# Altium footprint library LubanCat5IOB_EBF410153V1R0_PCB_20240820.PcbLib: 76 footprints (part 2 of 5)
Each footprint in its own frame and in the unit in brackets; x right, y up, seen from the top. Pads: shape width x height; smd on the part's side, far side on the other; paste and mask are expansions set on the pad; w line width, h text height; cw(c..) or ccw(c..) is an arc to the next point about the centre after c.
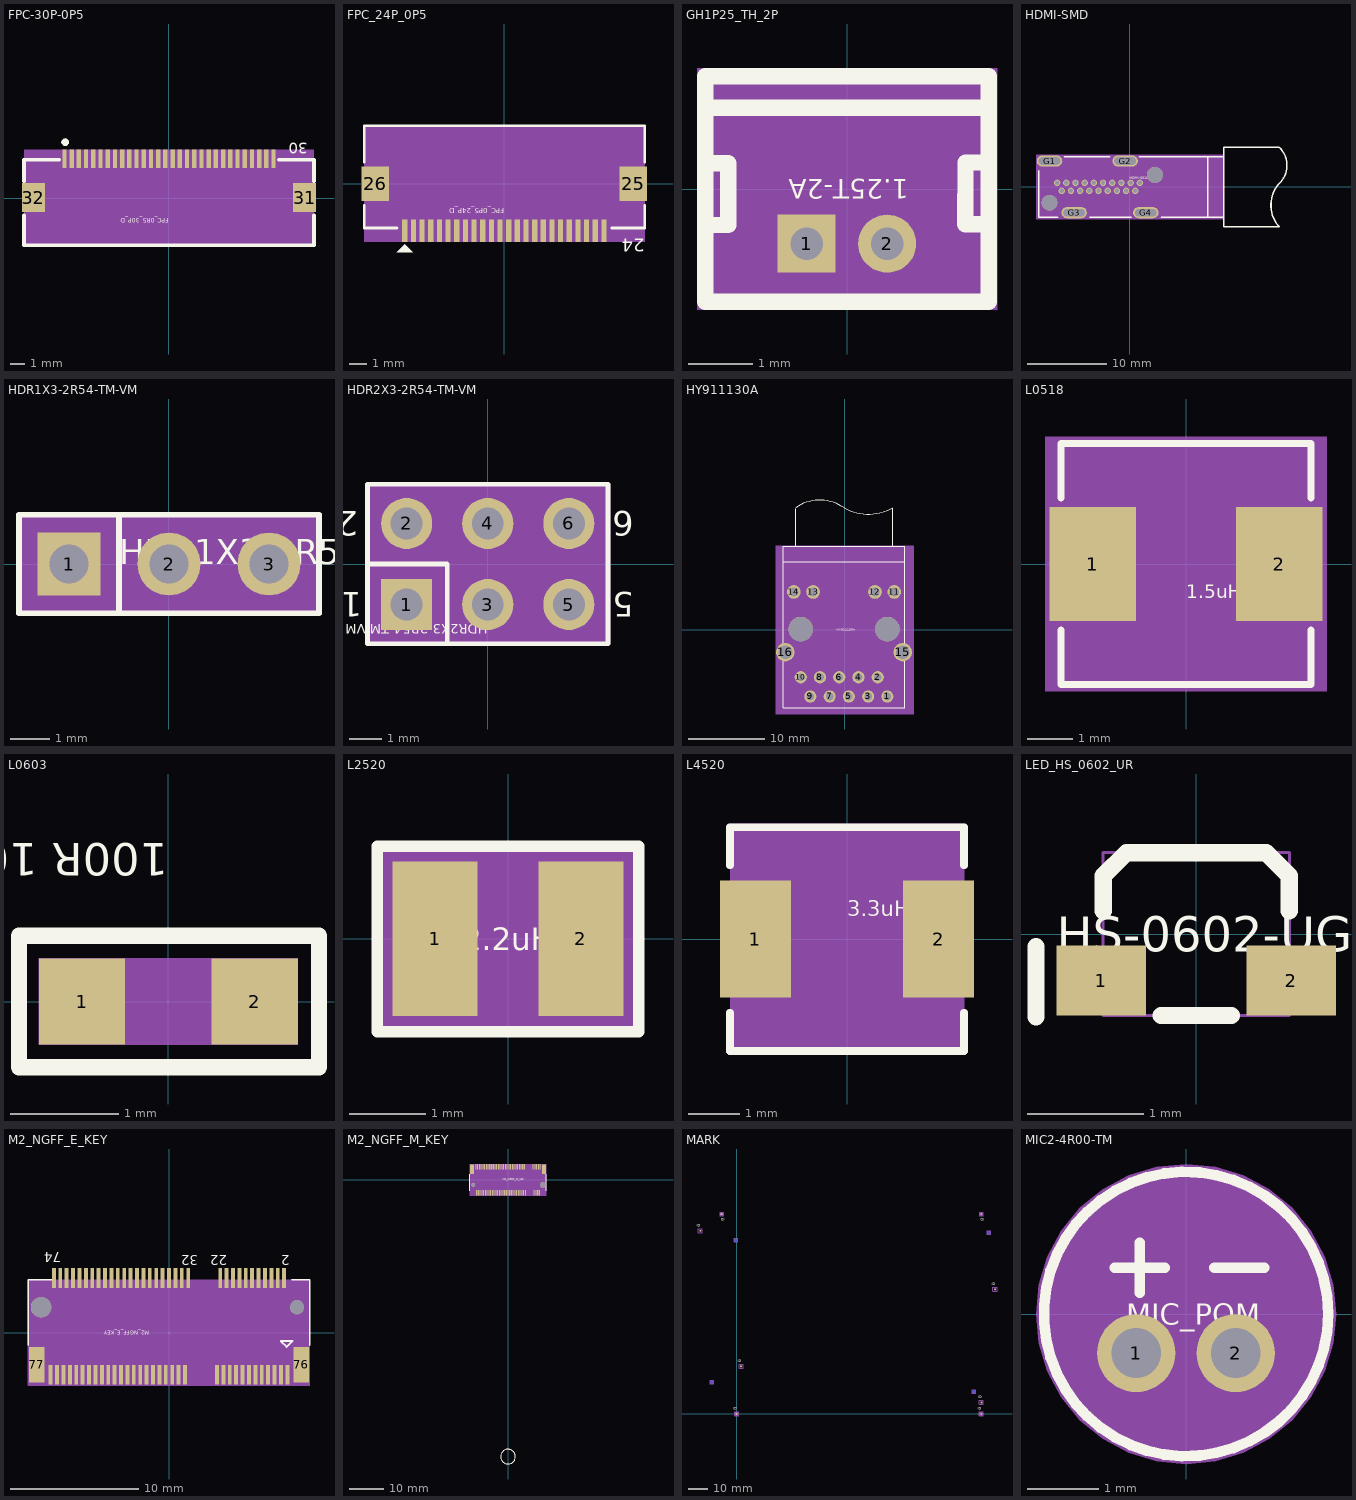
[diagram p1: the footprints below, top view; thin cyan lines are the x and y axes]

## FPC-30P-0P5 [mm] "FPC-30P-0P5"
pads (32):
  rect 0.3x1.3 smd: 1(-7.25,2.733) 2(-6.75,2.733) 3(-6.25,2.733) 4(-5.75,2.733) 5(-5.25,2.733) 6(-4.75,2.733) 7(-4.25,2.733) 8(-3.75,2.733) 9(-3.25,2.733) 10(-2.75,2.733) 11(-2.25,2.733) 12(-1.75,2.733) 13(-1.25,2.733) 14(-0.75,2.733) 15(-0.25,2.733) 16(0.25,2.733) 17(0.75,2.733) 18(1.25,2.733) 19(1.75,2.733) 20(2.25,2.733) 21(2.75,2.733) 22(3.25,2.733) 23(3.75,2.733) 24(4.25,2.733) 25(4.75,2.733) 26(5.25,2.733) 27(5.75,2.733) 28(6.25,2.733) 29(6.75,2.733) 30(7.25,2.733)
  rect 1.6x2 smd: 31(9.4,0.032) 32(-9.4,0.032)
Top Overlay:
  dashed: -7.2,4.137 -7.297,4.118 -7.38,4.063 -7.435,3.98 -7.455,3.882 -7.435,3.785 -7.417,3.757 -7.38,3.702 -7.297,3.647 -7.2,3.628 -7.102,3.647 -7.02,3.702 -6.983,3.757 -6.964,3.785 -6.945,3.882 -6.964,3.98 -7.02,4.063 -7.102,4.118
  lines w0.254: -10.05,-1.199 -10.05,-3.257 ; -10.05,1.164 -10.05,2.652 -7.631,2.652 ; 7.631,2.652 10.05,2.652 10.05,1.164 ; 10.05,-1.199 10.05,-3.268 -10.04,-3.268 -10.05,-3.257 ; -10.05,-3.257 -10.05,-3.257
  text "FPC_0R5_30P_D" at 0,-1.41 h0.3
  text "30" at 9.607,3.852 h0.76
Top 3D Body:
  region: 10.052,-3.35 10.052,3.35 -10.052,3.35 -10.052,-3.35
Mechanical 15:
  text "30" at 7.25,2.572 h0.1
  text "9" at -3.25,2.652 h0.1
  text "10" at -2.75,2.572 h0.1
  text "22" at 3.25,2.572 h0.1
  text "31" at 8.89,0.112 h0.1
  text "25" at 4.75,2.572 h0.1
  text "28" at 6.25,2.572 h0.1
  text "19" at 1.75,2.572 h0.1
  text "16" at 0.25,2.572 h0.1
  text "32" at -10.16,0.112 h0.1
  text "7" at -4.25,2.652 h0.1
  text "6" at -4.75,2.652 h0.1
  text "8" at -3.75,2.652 h0.1
  text "18" at 1.25,2.572 h0.1
  text "21" at 2.75,2.572 h0.1
  text "27" at 5.75,2.572 h0.1
  text "24" at 4.25,2.572 h0.1
  text "11" at -2.25,2.572 h0.1
  text "17" at 0.75,2.572 h0.1
  text "4" at -5.75,2.652 h0.1
  text "5" at -5.25,2.652 h0.1
  text "13" at -1.25,2.572 h0.1
  text "12" at -1.75,2.572 h0.1
  text "15" at -0.25,2.572 h0.1
  text "1" at -7.25,2.652 h0.1
  text "3" at -6.25,2.652 h0.1
  text "2" at -6.75,2.652 h0.1
  text "29" at 6.75,2.572 h0.1
  text "23" at 3.75,2.572 h0.1
  text "20" at 2.25,2.572 h0.1
  text "26" at 5.25,2.572 h0.1
  text "14" at -0.75,2.572 h0.1
3D body: height 3.81, standoff 0, extent -10.052,-3.35 10.052,3.35

## FPC_24P_0P5 [mm] "FPC_24P_0P5"
pads (26):
  rect 0.3x1.3 smd: 1(-5.75,-2.701) 2(-5.25,-2.701) 3(-4.75,-2.701) 4(-4.25,-2.701) 5(-3.75,-2.701) 6(-3.25,-2.701) 7(-2.75,-2.701) 8(-2.25,-2.701) 9(-1.75,-2.701) 10(-1.25,-2.701) 11(-0.75,-2.701) 12(-0.25,-2.701) 13(0.25,-2.701) 14(0.75,-2.701) 15(1.25,-2.701) 16(1.75,-2.701) 17(2.25,-2.701) 18(2.75,-2.701) 19(3.25,-2.701) 20(3.75,-2.701) 21(4.25,-2.701) 22(4.75,-2.701) 23(5.25,-2.701) 24(5.75,-2.701)
  rect 1.6x2 smd: 25(7.45,0.001) 26(-7.45,0.001)
Top Overlay:
  dashed: -6.199,-3.95 -5.301,-3.95 -5.75,-3.501
  lines w0.15: -8.1,-1.25 -8.1,-2.55 -6.2,-2.55 ; -8.1,1.25 -8.1,3.35 8.1,3.35 8.1,1.25 ; 6.2,-2.55 8.1,-2.55 8.1,-1.25
  text "FPC_0P5_24P_D" at 0,-1.41 h0.3
  text "24" at 8.109,-3.161 h0.76
Top 3D Body:
  region: -8.1,-3.35 8.1,-3.35 8.1,3.35 -8.1,3.35
Mechanical 15:
  text "8" at -2.25,-2.955 h0.64
  text "18" at 2.75,-3.209 h0.64
  text "23" at 5.25,-3.209 h0.64
  text "4" at -4.25,-2.955 h0.64
  text "21" at 4.25,-3.209 h0.64
  text "24" at 5.75,-3.209 h0.64
  text "26" at -7.45,-0.507 h0.64
  text "25" at 7.45,-0.507 h0.64
  text "11" at -0.75,-3.209 h0.64
  text "6" at -3.25,-2.955 h0.64
  text "5" at -3.75,-2.955 h0.64
  text "12" at -0.25,-3.209 h0.64
  text "9" at -1.75,-2.955 h0.64
  text "7" at -2.75,-2.955 h0.64
  text "10" at -1.25,-3.209 h0.64
  text "22" at 4.75,-3.209 h0.64
  text "15" at 1.25,-3.209 h0.64
  text "1" at -5.75,-2.955 h0.64
  text "2" at -5.25,-2.955 h0.64
  text "3" at -4.75,-2.955 h0.64
  text "20" at 3.75,-3.209 h0.64
  text "19" at 3.25,-3.209 h0.64
  text "17" at 2.25,-3.209 h0.64
  text "16" at 1.75,-3.209 h0.64
  text "14" at 0.75,-3.209 h0.64
  text "13" at 0.25,-3.209 h0.64
3D body: height 3.81, standoff 0, extent -8.1,-3.35 8.1,3.35

## GH1P25_TH_2P [mm] "GH1P25_TH_2P"
pads (2):
  rect 0.9x0.9 / inner round 1.524 / far side rect 0.9x0.9 hole 0.5: 1(-0.626,-0.849)
  round 0.9 hole 0.5: 2(0.624,-0.849)
Top Overlay:
  lines w0.254: -2.202,0.401 -1.841,0.401 -1.841,-0.559 -2.161,-0.559 ; -2.201,1.262 2.199,1.262 ; 2.159,-0.549 1.839,-0.548 1.839,0.411 2.2,0.411 ; 2.199,-1.749 -2.201,-1.749 -2.201,1.751 2.199,1.751 ; 2.202,-1.751 2.202,1.749
  text "1.25T-2A" at 0.96,0.15 h0.3
Bottom Overlay:
  lines w0.2: -0.001,-1.549 -0.001,-0.149
  lines w0.3: -1.401,-1.549 -1.401,-0.149 1.399,-0.149 1.399,-1.549 -1.101,-1.549 -1.401,-1.549
Top 3D Body:
  region: -2.329,-1.878 2.329,-1.878 2.329,1.878 -2.329,1.878
Mechanical 15:
  text "2" at 0.878,-0.849 h0.64
  text "1" at -0.372,-0.849 h0.64
3D body: height 3.81, standoff 0, extent -2.329,-1.878 2.329,1.878

## HDMI-SMD [mm] "HDMI-SMD"
pads (25):
  round 0.8 / inner round 1.524 / far side round 0.8 hole 0.55: 1(1.276,0.5) 3(0.121,0.5) 4(-0.449,-0.5) 6(-1.605,-0.5) 7(-2.189,0.5) 9(-3.344,0.5) 10(-3.917,-0.5) 12(-5.073,-0.5) 13(-5.654,0.5) 14(-6.229,-0.5) 15(-6.809,0.5) 16(-7.385,-0.5) 18(-8.541,-0.5) 19(-9.119,0.5)
  round 0.8 hole 0.55: 2(0.707,-0.5) 5(-1.034,0.5) 8(-2.761,-0.5) 11(-4.499,0.5) 17(-7.964,0.5)
  oval 3.2x1.4 / inner round 1.524 / far side oval 3.2x1.4 hole 2.7 slot 0.9 at 90 deg: G1(-10.074,3.25) G2(-0.574,3.25) G3(-6.974,-3.25) G4(2.026,-3.25)
  round 1.999 hole 1.999 unplated: ""(-10.074,-2) ""(3.176,1.5)
Top Overlay:
  lines w0.2: -11.43,2 -11.43,-3.833 -9.024,-3.833 ; -8.213,3.786 -2.535,3.786 ; -5.024,-3.834 0.176,-3.834 ; 1.233,3.786 11.812,3.786 ; 3.976,-3.834 11.812,-3.834 ; 18.776,5 cw(c16.636,2.7) 18.776,0.4 ccw(c21.856,-2.292) 18.812,-5.024 11.812,-5.024 11.812,4.976 18.812,4.976 ; 11.812,-3.834 9.812,-3.834 9.812,3.786 11.812,3.786 ; 11.812,-3.834 11.812,3.786
  text "HDMI-001C" at 0,0.93 h0.3
Top 3D Body:
  region: -11.776,-4.052 11.776,-4.052 11.776,4.052 -11.776,4.052
Mechanical 15:
  text "19" at -9.119,1.008 h0.64
  text "16" at -7.385,0.008 h0.64
  text "15" at -6.809,1.008 h0.64
  text "13" at -5.654,1.008 h0.64
  text "12" at -5.073,0.008 h0.64
  text "10" at -3.917,0.008 h0.64
  text "8" at -2.761,-0.246 h0.64
  text "5" at -1.034,0.754 h0.64
  text "2" at 0.707,-0.246 h0.64
  text "17" at -7.964,1.008 h0.64
  text "11" at -4.499,1.008 h0.64
  text "9" at -3.344,0.754 h0.64
  text "7" at -2.189,0.754 h0.64
  text "6" at -1.605,-0.246 h0.64
  text "4" at -0.449,-0.246 h0.64
  text "3" at 0.121,0.754 h0.64
  text "1" at 1.276,0.754 h0.64
  text "18" at -8.541,0.008 h0.64
  text "G1" at -10.074,3.758 h0.64
  text "G2" at -0.574,3.758 h0.64
  text "G4" at 2.026,-2.742 h0.64
  text "G3" at -6.974,-2.742 h0.64
  text "14" at -6.229,0.008 h0.64
3D body: height 3.81, standoff 0, extent -11.776,-4.052 11.776,4.052

## HDR1X3-2R54-TM-VM [mm] "HDR1X3-2R54-TM-VM"
pads (3):
  rect 1.6x1.6 / inner round 1.524 / far side rect 1.6x1.6 hole 1: 1(-2.535,0)
  round 1.6 / inner round 1.524 / far side round 1.6 hole 1: 2(0.005,0)
  round 1.6 hole 1: 3(2.545,0)
Top Overlay:
  lines w0.15: -1.265,-1.25 -1.265,1.25 ; -1.265,1.25 3.815,1.25 3.815,-1.25 -3.805,-1.25 -3.805,1.25 -1.265,1.25
  text "HDR1X3-2R54-TM-VM" at -1.265,0 h0.64
Bottom Overlay:
  lines w0.5: -1.265,-0.6 -1.265,0.6 ; 1.275,-0.6 1.275,0.6
Top 3D Body:
  region: -3.805,1.25 -3.805,-1.25 3.805,-1.25 3.805,1.25
Mechanical 15:
  text "3" at 2.545,-0.254 h0.64
  text "2" at 0.005,-0.254 h0.64
  text "1" at -2.535,-0.254 h0.64
Top Assembly:
  lines w0.15: -3.805,-1.25 3.815,-1.25 3.815,1.25 -3.805,1.25 -3.805,-1.25
3D body: height 3.81, standoff 0, extent -3.805,-1.25 3.805,1.25

## HDR2X3-2R54-TM-VM [mm] "HDR2X3-2R54-TM-VM"
pads (6):
  rect 1.6x1.6 / inner round 1.524 / far side rect 1.6x1.6 hole 1: 1(-2.54,-1.27)
  round 1.6 / inner round 1.524 / far side round 1.6 hole 1: 2(-2.54,1.27) 3(0,-1.27) 4(0,1.27) 5(2.54,-1.27) 6(2.54,1.27)
Top Overlay:
  lines w0.15: -3.77,0 -1.27,0 -1.27,-2.5 ; -3.77,-2.5 3.77,-2.5 3.77,2.5 -3.77,2.5 -3.77,-2.5
  text "HDR2X3-2R54-TM-VM" at 0,-1.89 h0.3
  text "1" at -3.937,-0.889 h0.76
  text "5" at 4.572,-0.889 h0.76
  text "2" at -4.064,1.651 h0.76
  text "6" at 4.572,1.651 h0.76
Bottom Overlay:
  lines w0.5: -3.17,0 3.17,0 ; -1.27,-1.9 -1.27,1.9 ; 1.27,-1.9 1.27,1.9
Top 3D Body:
  region: -3.8,2.5 -3.8,-2.5 3.8,-2.5 3.8,2.5
Mechanical 15:
  text "6" at 2.54,1.016 h0.64
  text "3" at 0,-1.524 h0.64
  text "2" at -2.54,1.016 h0.64
  text "1" at -2.54,-1.524 h0.64
  text "4" at 0,1.016 h0.64
  text "5" at 2.54,-1.524 h0.64
Top Assembly:
  lines w0.15: -3.77,-2.5 -3.77,2.5 3.77,2.5 3.77,-2.5 -3.77,-2.5
3D body: height 3.81, standoff 0, extent -3.8,-2.5 3.8,2.5

## HY911130A [mm] "HY911130A"
pads (18):
  round 1.6 / inner round 1.524 / far side round 1.6 hole 1: 1(5.629,-8.79) 2(4.359,-6.25) 3(3.089,-8.79) 4(1.819,-6.25) 5(0.549,-8.79) 6(-0.721,-6.25) 7(-1.991,-8.79) 8(-3.261,-6.25) 9(-4.531,-8.79)
  round 1.6 hole 1: 10(-5.801,-6.25)
  round 1.8 / inner round 1.524 / far side round 1.8 hole 1.2: 11(6.534,5) 12(3.994,5) 13(-4.177,5) 14(-6.717,5)
  round 2.43 / inner round 1.524 / far side round 2.43 hole 1.83: 15(7.654,-2.95) 16(-7.836,-2.95)
  round 3.25 hole 3.25 unplated: ""(-5.806,0.1) ""(5.624,0.1)
Top Overlay:
  lines w0.15: -6.492,16 -6.492,11 6.309,11 6.309,16 ; -6.492,16.1 cw(c-3.291,11.5) -0.091,16.1 ccw(c3.109,21.875) 6.309,16.1 ; -8.111,11 -8.111,9 7.929,9 ; -8.111,11 -8.111,-10.3 7.929,-10.3 7.929,9 ; -8.111,11 7.929,11 7.929,9
  text "HY911130A" at -1.08,-0.15 h0.3
Bottom Overlay:
  drawing of 17 lines, arcs and shapes, not listed
Top 3D Body:
  region: -9.108,11.1 -9.108,-11.1 9.109,-11.1 9.109,11.1
Mechanical 15:
  text "2" at 3.952,-6.25 h1.02
  text "9" at -4.938,-8.79 h1.02
  text "8" at -3.668,-6.25 h1.02
  text "6" at -1.128,-6.25 h1.02
  text "5" at 0.142,-8.79 h1.02
  text "7" at -2.398,-8.79 h1.02
  text "4" at 1.412,-6.25 h1.02
  text "3" at 2.682,-8.79 h1.02
  text "10" at -6.614,-6.25 h1.02
  text "12" at 3.181,5 h1.02
  text "15" at 6.841,-2.95 h1.02
  text "16" at -8.649,-2.95 h1.02
  text "1" at 5.222,-8.79 h1.02
  text "13" at -4.989,5 h1.02
  text "11" at 5.721,5 h1.02
  text "14" at -7.529,5 h1.02
3D body: height 3.81, standoff 0, extent -9.108,-11.1 9.109,11.1

## L0518 [mm] "L0518"
pads (2):
  rect 1.9x2.5 smd: 1(-2.05,0) 2(2.05,0)
Top Overlay:
  lines w0.15: -2.75,-1.45 -2.75,-2.65 2.75,-2.65 2.75,-1.45 ; -2.75,1.45 -2.75,2.65 2.75,2.65 2.75,1.45
  text "1.5uH" at 0,-0.75 h0.3
Top 3D Body:
  region: -3.1,2.8 -3.1,-2.8 3.1,-2.8 3.1,2.8
Mechanical 15:
  text "1" at -1.9,-0.708 h0.64
  text "2" at 2.2,-0.808 h0.64
Top Assembly:
  lines w0.15: -2.75,-1.45 -2.75,-2.65 2.75,-2.65 2.75,-1.45 ; -2.75,1.45 -2.75,2.65 2.75,2.65 2.75,1.45
3D body: height 3.81, standoff 0, extent -3.1,-2.8 3.1,2.8

## L0603 [mil] "L0603"
pads (2):
  rect 31.5x31.5 smd: 1(-31.5,0) 2(31.5,0)
Top Overlay:
  lines w6: -54.5,-24 55,-24 55,24 -54.5,24 -54.5,-24
  text "100R 100MHz" at -0.01,57.87 h11.81
Top 3D Body:
  region: -47.24,-15.75 -47.24,15.75 47.24,15.75 47.24,-15.75
Mechanical 15:
  text "2" at 31.5,18 h45
  text "1" at -31.5,18 h45
3D body: height 150, standoff 0, extent -47.24,-15.75 47.24,15.75

## L2520 [mil] "L2520"
pads (2):
  rect 44x80 smd: 1(-37.75,0) 2(37.75,0)
Top Overlay:
  lines w6: -67.68,-48.15 -67.68,47.92 67.67,47.92 67.67,-48.15 -67.67,-48.15 -67.68,-48.15
  text "2.2uH" at -23.62,-5.91 h11.81
Top 3D Body:
  region: -65,-45 65,-45 65,45 -65,45
Mechanical 15:
  text "1" at -42.47,0 h11.81
  text "2" at 33.03,0 h11.81
3D body: height 150, standoff 0, extent -65,-45 65,45

## L4520 [mm] "L4520"
pads (2):
  rect 1.4x2.3 smd: 1(-1.803,-0.002) 2(1.798,-0.002)
Top Overlay:
  lines w0.15: -2.302,-1.452 -2.302,-2.202 2.298,-2.202 2.298,-1.452 ; -2.302,1.448 -2.302,2.198 2.298,2.198 2.298,1.448
  text "3.3uH" at 0,0.45 h0.3
Top 3D Body:
  region: -2.302,-2.202 2.303,-2.202 2.303,2.203 -2.302,2.203
Mechanical 15:
  text "2" at 1.798,0.252 h0.64
  text "1" at -1.803,0.252 h0.64
Top Assembly:
  lines w0.15: -2.302,-1.452 -2.302,-2.202 2.298,-2.202 2.298,-1.452 ; -2.302,1.448 -2.302,2.198 2.298,2.198 2.298,1.448
3D body: height 3.81, standoff 0, extent -2.302,-2.202 2.303,2.203

## LED_HS_0602_UR [mm] "LED_HS_0602_UR"
pads (2):
  rect 0.77x0.599 smd: 1(-0.815,-0.4) 2(0.815,-0.4)
Top Overlay:
  lines w0.15: -1.377,-0.71 -1.377,-0.11 ; -0.8,0.199 -0.8,0.499 -0.599,0.7 0.599,0.7 0.8,0.499 0.8,0.199 ; -0.3,-0.7 0.3,-0.7
  text "HS-0602-UG" at -1.2,-0.15 h0.3
Top 3D Body:
  lines w0.025: -0.8,-0.7 0.8,-0.7 0.8,0.7 -0.8,0.7 -0.8,-0.7
Mechanical 15:
  text "2" at 0.695,-0.4 h0.3
  text "1" at -0.935,-0.4 h0.3

## M2_NGFF_E_KEY [mm] "M2_NGFF_E_KEY"
pads (71):
  rect 0.3x1.55 smd: 1(9.25,-3.3) 2(9,4.25) 3(8.75,-3.3) 4(8.5,4.25) 5(8.25,-3.3) 6(8,4.25) 7(7.75,-3.3) 8(7.5,4.25) 9(7.25,-3.3) 10(7,4.25) 11(6.75,-3.3) 12(6.5,4.25) 13(6.25,-3.3) 14(6,4.25) 15(5.75,-3.3) 16(5.5,4.25) 17(5.25,-3.3) 18(5,4.25) 19(4.75,-3.3) 20(4.5,4.25) 21(4.25,-3.3) 22(4,4.25) 23(3.75,-3.3) 32(1.5,4.25) 33(1.25,-3.3) 34(1,4.25) 35(0.75,-3.3) 36(0.5,4.25) 37(0.25,-3.3) 38(0,4.25) 39(-0.25,-3.3) 40(-0.5,4.25) 41(-0.75,-3.3) 42(-1,4.25) 43(-1.25,-3.3) 44(-1.5,4.25) 45(-1.75,-3.3) 46(-2,4.25) 47(-2.25,-3.3) 48(-2.5,4.25) 49(-2.75,-3.3) 50(-3,4.25) 51(-3.25,-3.3) 52(-3.5,4.25) 53(-3.75,-3.3) 54(-4,4.25) 55(-4.25,-3.3) 56(-4.5,4.25) 57(-4.75,-3.3) 58(-5,4.25) 59(-5.25,-3.3) 60(-5.5,4.25) 61(-5.75,-3.3) 62(-6,4.25) 63(-6.25,-3.3) 64(-6.5,4.25) 65(-6.75,-3.3) 66(-7,4.25) 67(-7.25,-3.3) 68(-7.5,4.25) 69(-7.75,-3.3) 70(-8,4.25) 71(-8.25,-3.3) 72(-8.5,4.25) 73(-8.75,-3.3) 74(-9,4.25) 75(-9.25,-3.3)
  rect 1.2x2.75 smd: 76(10.35,-2.525) 77(-10.35,-2.525)
  round 1.6 hole 1.6 unplated: ""(-10,1.975)
  round 1.1 hole 1.1 unplated: ""(10,1.975)
Top Overlay:
  lines w0.15: -11,-0.975 -11,4.125 -9.1,4.125 ; 9.6,4.125 11,4.125 11,-0.975 ; 8.75,-0.675 9.65,-0.675 9.2,-1.125 8.75,-0.675
  text "M2_NGFF_E_KEY" at -1.56,0.15 h0.3
  text "74" at -8.418,6.26 h0.76
  text "2" at 9.45,6.052 h0.76
  text "22" at 4.55,6.052 h0.76
  text "32" at 2.3,6.052 h0.76
Top 3D Body:
  region: 11,4.125 -11,4.125 -11,-4.125 11,-4.125
Mechanical 15:
  text "47" at -2.603,-3.35 h0.25
  text "49" at -3.103,-3.35 h0.25
  text "43" at -1.603,-3.35 h0.25
  text "18" at 4.647,4.25 h0.25
  text "7" at 7.417,-3.5 h0.25
  text "33" at 0.897,-3.35 h0.25
  text "45" at -2.103,-3.35 h0.25
  text "51" at -3.603,-3.35 h0.25
  text "39" at -0.603,-3.35 h0.25
  text "57" at -5.103,-3.35 h0.25
  text "63" at -6.603,-3.35 h0.25
  text "69" at -8.103,-3.35 h0.25
  text "75" at -9.603,-3.35 h0.25
  text "77" at -10.858,-2.525 h0.64
  text "76" at 9.842,-2.525 h0.64
  text "1" at 8.917,-3.5 h0.25
  text "37" at -0.103,-3.35 h0.25
  text "56" at -4.853,4.25 h0.25
  text "52" at -3.853,4.25 h0.25
  text "55" at -4.603,-3.35 h0.25
  text "5" at 7.917,-3.5 h0.25
  text "53" at -4.103,-3.35 h0.25
  text "35" at 0.397,-3.35 h0.25
  text "3" at 8.417,-3.5 h0.25
  text "4" at 8.248,4.25 h0.25
  text "2" at 8.667,4.05 h0.25
  text "74" at -9.353,4.25 h0.25
  text "72" at -8.853,4.25 h0.25
  text "41" at -1.103,-3.35 h0.25
  text "54" at -4.353,4.25 h0.25
  text "42" at -1.353,4.25 h0.25
  text "40" at -0.853,4.25 h0.25
  text "38" at -0.353,4.25 h0.25
  text "66" at -7.353,4.25 h0.25
  text "70" at -8.353,4.25 h0.25
  text "68" at -7.853,4.25 h0.25
  text "20" at 4.147,4.25 h0.25
  text "32" at 1.147,4.25 h0.25
  text "22" at 3.647,4.25 h0.25
  text "36" at 0.147,4.25 h0.25
  text "34" at 0.647,4.25 h0.25
  text "50" at -3.353,4.25 h0.25
  text "21" at 3.714,-3.65 h0.25
  text "23" at 3.214,-3.65 h0.25
  text "19" at 4.214,-3.65 h0.25
  text "17" at 4.714,-3.65 h0.25
  text "15" at 5.214,-3.65 h0.25
  text "13" at 5.714,-3.65 h0.25
  text "11" at 6.214,-3.65 h0.25
  text "9" at 6.917,-3.5 h0.25
  text "71" at -8.603,-3.35 h0.25
  text "73" at -9.103,-3.35 h0.25
  text "59" at -5.603,-3.35 h0.25
  text "61" at -6.103,-3.35 h0.25
  text "65" at -7.103,-3.35 h0.25
  text "67" at -7.603,-3.35 h0.25
  text "64" at -6.853,4.25 h0.25
  text "10" at 6.647,4.25 h0.25
  text "14" at 5.647,4.25 h0.25
  text "12" at 6.147,4.25 h0.25
  text "8" at 7.248,4.25 h0.25
  text "16" at 5.147,4.25 h0.25
  text "6" at 7.748,4.25 h0.25
  text "58" at -5.353,4.25 h0.25
  text "60" at -5.853,4.25 h0.25
  text "48" at -2.853,4.25 h0.25
  text "46" at -2.353,4.25 h0.25
  text "44" at -1.853,4.25 h0.25
  text "62" at -6.353,4.25 h0.25
Top Assembly:
  lines w0.025: -11,-4.125 -11,4.125 11,4.125 11,-4.125 -11,-4.125
3D body: height 3.81, standoff 0, extent -11,-4.125 11,4.125

## M2_NGFF_M_KEY [mm] "M2_NGFF_M_KEY"
pads (71):
  rect 0.3x1.55 smd: 1(-9.25,3.762) 2(-9,-3.687) 3(-8.75,3.762) 4(-8.5,-3.687) 5(-8.25,3.762) 6(-8,-3.687) 7(-7.75,3.762) 8(-7.5,-3.687) 9(-7.25,3.762) 10(-7,-3.687) 11(-6.75,3.762) 12(-6.5,-3.687) 13(-6.25,3.762) 14(-6,-3.687) 15(-5.75,3.762) 16(-5.5,-3.687) 17(-5.25,3.762) 18(-5,-3.687) 19(-4.75,3.762) 20(-4.5,-3.687) 21(-4.25,3.762) 22(-4,-3.687) 23(-3.75,3.762) 24(-3.5,-3.687) 25(-3.25,3.762) 26(-3,-3.687) 27(-2.75,3.762) 28(-2.5,-3.687) 29(-2.25,3.762) 30(-2,-3.687) 31(-1.75,3.762) 32(-1.5,-3.687) 33(-1.25,3.762) 34(-1,-3.687) 35(-0.75,3.762) 36(-0.5,-3.687) 37(-0.25,3.762) 38(0,-3.687) 39(0.25,3.762) 40(0.5,-3.687) 41(0.75,3.762) 42(1,-3.687) 43(1.25,3.762) 44(1.5,-3.687) 45(1.75,3.762) 46(2,-3.687) 47(2.25,3.762) 48(2.5,-3.687) 49(2.75,3.762) 50(3,-3.687) 51(3.25,3.762) 52(3.5,-3.687) 53(3.75,3.762) 54(4,-3.687) 55(4.25,3.762) 56(4.5,-3.687) 57(4.75,3.762) 58(5,-3.687) 67(7.25,3.762) 68(7.5,-3.687) 69(7.75,3.762) 70(8,-3.687) 71(8.25,3.762) 72(8.5,-3.687) 73(8.75,3.762) 74(9,-3.687) 75(9.25,3.762)
  rect 1.2x2.75 smd: 76(10.35,3.062) 77(-10.35,3.062)
  round 1.1 hole 1.1 unplated: ""(-10,-1.438)
  round 1.6 hole 1.6 unplated: ""(10,-1.438)
Top Overlay:
  circle w0.127: c0,-79.688 r2.11
  lines w0.127: -10.95,-3.128 -10.95,1.608 ; 10.95,-3.128 10.95,1.608
  text "M2_NGFF_M_KEY" at -1.56,-0.15 h0.3
Top 3D Body:
  region: -10.95,-4.563 10.95,-4.563 10.95,4.563 -10.95,4.563
Mechanical 15:
  text "31" at -2.258,3.762 h0.64
  text "29" at -2.758,3.762 h0.64
  text "77" at -10.858,3.062 h0.64
  text "76" at 9.842,3.062 h0.64
  text "3" at -9.004,3.762 h0.64
  text "9" at -7.504,3.762 h0.64
  text "15" at -6.258,3.762 h0.64
  text "21" at -4.758,3.762 h0.64
  text "71" at 7.692,3.437 h0.64
  text "75" at 8.792,3.437 h0.64
  text "27" at -3.258,3.762 h0.64
  text "33" at -1.758,3.762 h0.64
  text "39" at -0.258,3.762 h0.64
  text "57" at 4.242,3.762 h0.64
  text "51" at 2.742,3.762 h0.64
  text "45" at 1.242,3.762 h0.64
  text "73" at 8.292,3.437 h0.64
  text "1" at -9.504,3.762 h0.64
  text "47" at 1.742,3.762 h0.64
  text "37" at -0.758,3.762 h0.64
  text "2" at -9.254,-3.687 h0.64
  text "4" at -8.754,-3.687 h0.64
  text "12" at -7.008,-3.687 h0.64
  text "14" at -6.508,-3.687 h0.64
  text "16" at -6.008,-3.687 h0.64
  text "18" at -5.508,-3.687 h0.64
  text "74" at 8.592,-3.963 h0.64
  text "70" at 7.392,-3.963 h0.64
  text "72" at 7.992,-3.963 h0.64
  text "35" at -1.258,3.762 h0.64
  text "49" at 2.242,3.762 h0.64
  text "38" at -0.508,-3.687 h0.64
  text "50" at 2.492,-3.687 h0.64
  text "10" at -7.508,-3.687 h0.64
  text "55" at 3.742,3.762 h0.64
  text "53" at 3.242,3.762 h0.64
  text "52" at 2.992,-3.687 h0.64
  text "43" at 0.742,3.762 h0.64
  text "54" at 3.492,-3.687 h0.64
  text "41" at 0.242,3.762 h0.64
  text "68" at 6.792,-3.963 h0.64
  text "13" at -6.758,3.762 h0.64
  text "25" at -3.758,3.762 h0.64
  text "11" at -7.258,3.762 h0.64
  text "23" at -4.258,3.762 h0.64
  text "7" at -8.004,3.762 h0.64
  text "19" at -5.258,3.762 h0.64
  text "5" at -8.504,3.762 h0.64
  text "17" at -5.758,3.762 h0.64
  text "32" at -2.008,-3.687 h0.64
  text "30" at -2.508,-3.687 h0.64
  text "28" at -3.008,-3.687 h0.64
  text "26" at -3.508,-3.687 h0.64
  text "24" at -4.008,-3.687 h0.64
  text "22" at -4.508,-3.687 h0.64
  text "20" at -5.008,-3.687 h0.64
  text "8" at -7.754,-3.687 h0.64
  text "67" at 6.392,3.437 h0.64
  text "48" at 1.992,-3.687 h0.64
  text "46" at 1.492,-3.687 h0.64
  text "44" at 0.992,-3.687 h0.64
  text "42" at 0.492,-3.687 h0.64
  text "40" at -0.008,-3.687 h0.64
  text "36" at -1.008,-3.687 h0.64
  text "34" at -1.508,-3.687 h0.64
  text "6" at -8.254,-3.687 h0.64
  text "58" at 4.492,-3.687 h0.64
  text "56" at 3.992,-3.687 h0.64
  text "69" at 7.292,3.437 h0.64
3D body: height 3.81, standoff 0, extent -10.95,-4.563 10.95,4.563

## MARK [mil] "MARK"
pads (12):
  round 40 smd: 1(-724.11,3646.43) 1(-300,3976.38) 1(0,0) 1(90.89,946.42) 1(4874.8,0) 1(4874.8,3976.38) 1(4875.89,225.43) 1(5148.89,2479.43)
  round 40 smd far side: 1(-499.11,632.42) 1(-17.11,3457.43) 1(4728.89,441.43) 1(5023.89,3605.43)
Top Overlay:
  text "ID" at 5083.89,2561.43 h50
  text "ID" at 4810.89,307.43 h50
  text "ID" at -789.11,3728.43 h50
  text "ID" at 25.89,1028.42 h50
  text "ID" at -235,3894.38 h50
  text "ID" at 4939.8,3894.38 h50
  text "ID" at 4809.8,82 h50
  text "ID" at -65,82 h50
Bottom Overlay:
  text "ID" at 4958.89,3523.43 h50
  text "ID" at -82.11,3375.43 h50
  text "ID" at -564.11,550.42 h50
  text "ID" at 4809.8,-82 h50
  text "ID" at 4809.8,3894.38 h50
  text "ID" at -365,3894.38 h50
  text "ID" at -65,-82 h50
Top 3D Body:
  region: -260,4016.38 -340,4016.38 -340,3936.38 -260,3936.38
  region: 4914.8,4016.38 4834.8,4016.38 4834.8,3936.38 4914.8,3936.38
  lines w1: -764.11,3606.43 -684.11,3606.43 -684.11,3686.43 -764.11,3686.43 -764.11,3606.43 ; -40,-40 40,-40 40,40 -40,40 -40,-40 ; 50.89,906.42 130.89,906.42 130.89,986.42 50.89,986.42 50.89,906.42 ; 4834.8,-40 4914.8,-40 4914.8,40 4834.8,40 4834.8,-40 ; 4835.89,185.43 4915.89,185.43 4915.89,265.43 4835.89,265.43 4835.89,185.43 ; 5108.89,2439.43 5188.89,2439.43 5188.89,2519.43 5108.89,2519.43 5108.89,2439.43
Bottom 3D Body:
  region: 4688.89,481.43 4688.89,401.43 4768.89,401.43 4768.89,481.43
  region: 4983.89,3645.43 4983.89,3565.43 5063.89,3565.43 5063.89,3645.43
  region: -57.11,3497.43 -57.11,3417.43 22.89,3417.43 22.89,3497.43
  region: -539.11,672.42 -539.11,592.42 -459.11,592.42 -459.11,672.42
  region: 4834.8,40 4834.8,-40 4914.8,-40 4914.8,40
  region: 4834.8,4016.38 4834.8,3936.38 4914.8,3936.38 4914.8,4016.38
  region: -340,4016.38 -340,3936.38 -260,3936.38 -260,4016.38
  region: -40,40 -40,-40 40,-40 40,40
Mechanical 15:
  text "1" at 4696.89,441.43 h40
  text "1" at 4991.89,3605.43 h40
  text "1" at -49.11,3457.43 h40
  text "1" at -531.11,632.42 h40
  text "1" at 5116.89,2479.43 h40
  text "1" at 4843.89,225.43 h40
  text "1" at -756.11,3646.43 h40
  text "1" at 58.89,946.42 h40
  text "1" at 4842.8,0 h40
  text "1" at 4842.8,3976.38 h40
  text "1" at -332,3976.38 h40
  text "1" at -32,0 h40
  text "1" at -332,3976.38 h40
  text "1" at 4842.8,3976.38 h40
  text "1" at 4842.8,0 h40
  text "1" at -32,0 h40
3D body: height 150, standoff 0, extent -340,3936.38 -260,4016.38
3D body: height 150, standoff 0, extent 4834.8,3936.38 4914.8,4016.38
3D body: height 150, standoff 0, extent 4688.89,401.43 4768.89,481.43
3D body: height 150, standoff 0, extent 4983.89,3565.43 5063.89,3645.43
3D body: height 150, standoff 0, extent -57.11,3417.43 22.89,3497.43
3D body: height 150, standoff 0, extent -539.11,592.42 -459.11,672.42
3D body: height 150, standoff 0, extent 4834.8,-40 4914.8,40
3D body: height 150, standoff 0, extent 4834.8,3936.38 4914.8,4016.38
3D body: height 150, standoff 0, extent -340,3936.38 -260,4016.38
3D body: height 150, standoff 0, extent -40,-40 40,40

## MIC2-4R00-TM [mm] "MIC2-4R00-TM"
pads (2):
  round 1.1 / inner round 1.524 / far side round 1.1 hole 0.7: 1(-0.7,-0.55) 2(0.7,-0.55)
Top Overlay:
  circle w0.15: c0,0 r2
  lines w0.15: -1,0.65 -0.3,0.65 ; -0.65,0.3 -0.65,1 ; 0.4,0.65 1.1,0.65
  text "MIC_POM" at -0.84,-0.15 h0.3
Top 3D Body:
  region: 2.11,0 2.07,0.412 1.95,0.808 1.755,1.172 1.492,1.492 1.172,1.755 0.808,1.95 0.412,2.07 0,2.11 -0.412,2.07 -0.808,1.95 -1.051,1.82 -1.172,1.755 -1.492,1.492 -1.755,1.172 -1.95,0.808 -2.07,0.412 -2.11,0 -2.07,-0.412 -1.95,-0.808 -1.755,-1.172 -1.492,-1.492 -1.172,-1.755 -1.051,-1.82 -0.808,-1.95 -0.412,-2.07 0,-2.11 0.412,-2.07 0.808,-1.95 1.172,-1.755 1.492,-1.492 1.755,-1.172 1.95,-0.808 2.07,-0.412
Mechanical 15:
  text "2" at 0.446,-0.55 h0.64
  text "1" at -0.954,-0.55 h0.64
Top Assembly:
  circle w0.15: c0,0 r2
3D body: height 3.81, standoff 0, extent -2.11,-2.11 2.11,2.11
